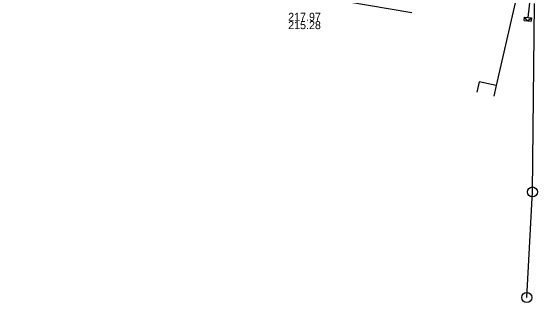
# Model space of a CAD drawing. Extents: x -596024 to -594475, y -1163820 to -1161957.
# Drawn here: x -595839.6 to -595787, y -1163095.5 to -1163066.3 of the extents above; entities that cross this region are included whole.
import ezdxf

# ---------------------------------------------------------------- set-up
doc = ezdxf.new("R2010")
doc.units = 0
for name, color, linetype in [('31', 7, 'Continuous'), ('Vrstva 11', 7, 'Continuous'), ('Vrstva 12', 7, 'Continuous'), ('Vrstva 13', 7, 'Continuous'), ('Vrstva 42', 7, 'Continuous'), ('Vrstva 43', 7, 'Continuous'), ('Vrstva 55', 7, 'Continuous'), ('Vrstva 9', 7, 'Continuous')]:
    doc.layers.add(name, color=color, linetype=linetype)

# ---------------------------------------------------------------- blocks, each defined once
blk = doc.blocks.new('NN630')
at = {"layer": '31'}
for points in [[(-0.003, -0.7), (-0.703, 0)], [(-0.703, -0.7), (-0.703, 0), (0.697, 0), (0.697, -0.7)], [(-0.003, -0.7), (0.697, 0)], [(-0.703, -0.7), (0.697, -0.7)]]:
    blk.add_lwpolyline(points, dxfattribs=at)

msp = doc.modelspace()

# ---------------------------------------------------------------- linework, layer by layer
at = {"layer": 'Vrstva 11'}
for centre in [(-595787.45, -1163084.45), (-595788.02, -1163095)]:
    msp.add_circle(centre, 0.5, dxfattribs=at)
at = {"layer": 'Vrstva 13'}
for points in [[(-595788.28, -1163061.624), (-595788.339, -1163061.881), (-595791.073, -1163073.813), (-595791.314, -1163074.865)], [(-595791.073, -1163073.813), (-595792.772, -1163073.424), (-595792.999, -1163074.461)]]:
    msp.add_lwpolyline(points, dxfattribs=at)
at = {"layer": 'Vrstva 42'}
msp.add_lwpolyline([(-595798.777, -1163059.052), (-595798.475, -1163058.861), (-595794.96, -1163060.79), (-595790.121, -1163061.78), (-595788.65, -1163062.369), (-595787.88, -1163063.252), (-595787.609, -1163064.339), (-595787.903, -1163066.989)], dxfattribs=at)
at = {"layer": 'Vrstva 55'}
msp.add_lwpolyline([(-595799.496, -1163066.55), (-595814.438, -1163063.953), (-595839.556, -1163058.185)], dxfattribs=at)
at = {"layer": 'Vrstva 9'}
msp.add_lwpolyline([(-595788.02, -1163095), (-595787.45, -1163084.45), (-595787.23, -1163065.61)], dxfattribs=at)

# ---------------------------------------------------------------- block references
at = {"layer": 'Vrstva 43', "xscale": 0.5, "yscale": 0.5000000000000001, "rotation": -5.999999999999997}
msp.add_blockref('NN630', (-595787.903, -1163066.989), dxfattribs=at)

# ---------------------------------------------------------------- texts
at = {"layer": 'Vrstva 12'}
for s, p in [('217.97', (-595811.842, -1163067.333)), ('215.28', (-595811.842, -1163068.165))]:
    msp.add_text(s, height=0.8, dxfattribs=at).set_placement(p)

doc.saveas('drawing.dxf')
